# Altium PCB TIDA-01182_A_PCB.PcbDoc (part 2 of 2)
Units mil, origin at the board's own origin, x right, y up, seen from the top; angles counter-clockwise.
Board outline 4950 x 3200 mil, 4 copper layers (Component Side, Signal Layer 1, Signal Layer 2, Solder Side), stack 61.2 mil thick; 169 components, 99 nets, 868 pads, 44 vias.
Unrouted connection lines stored in the file: 4.
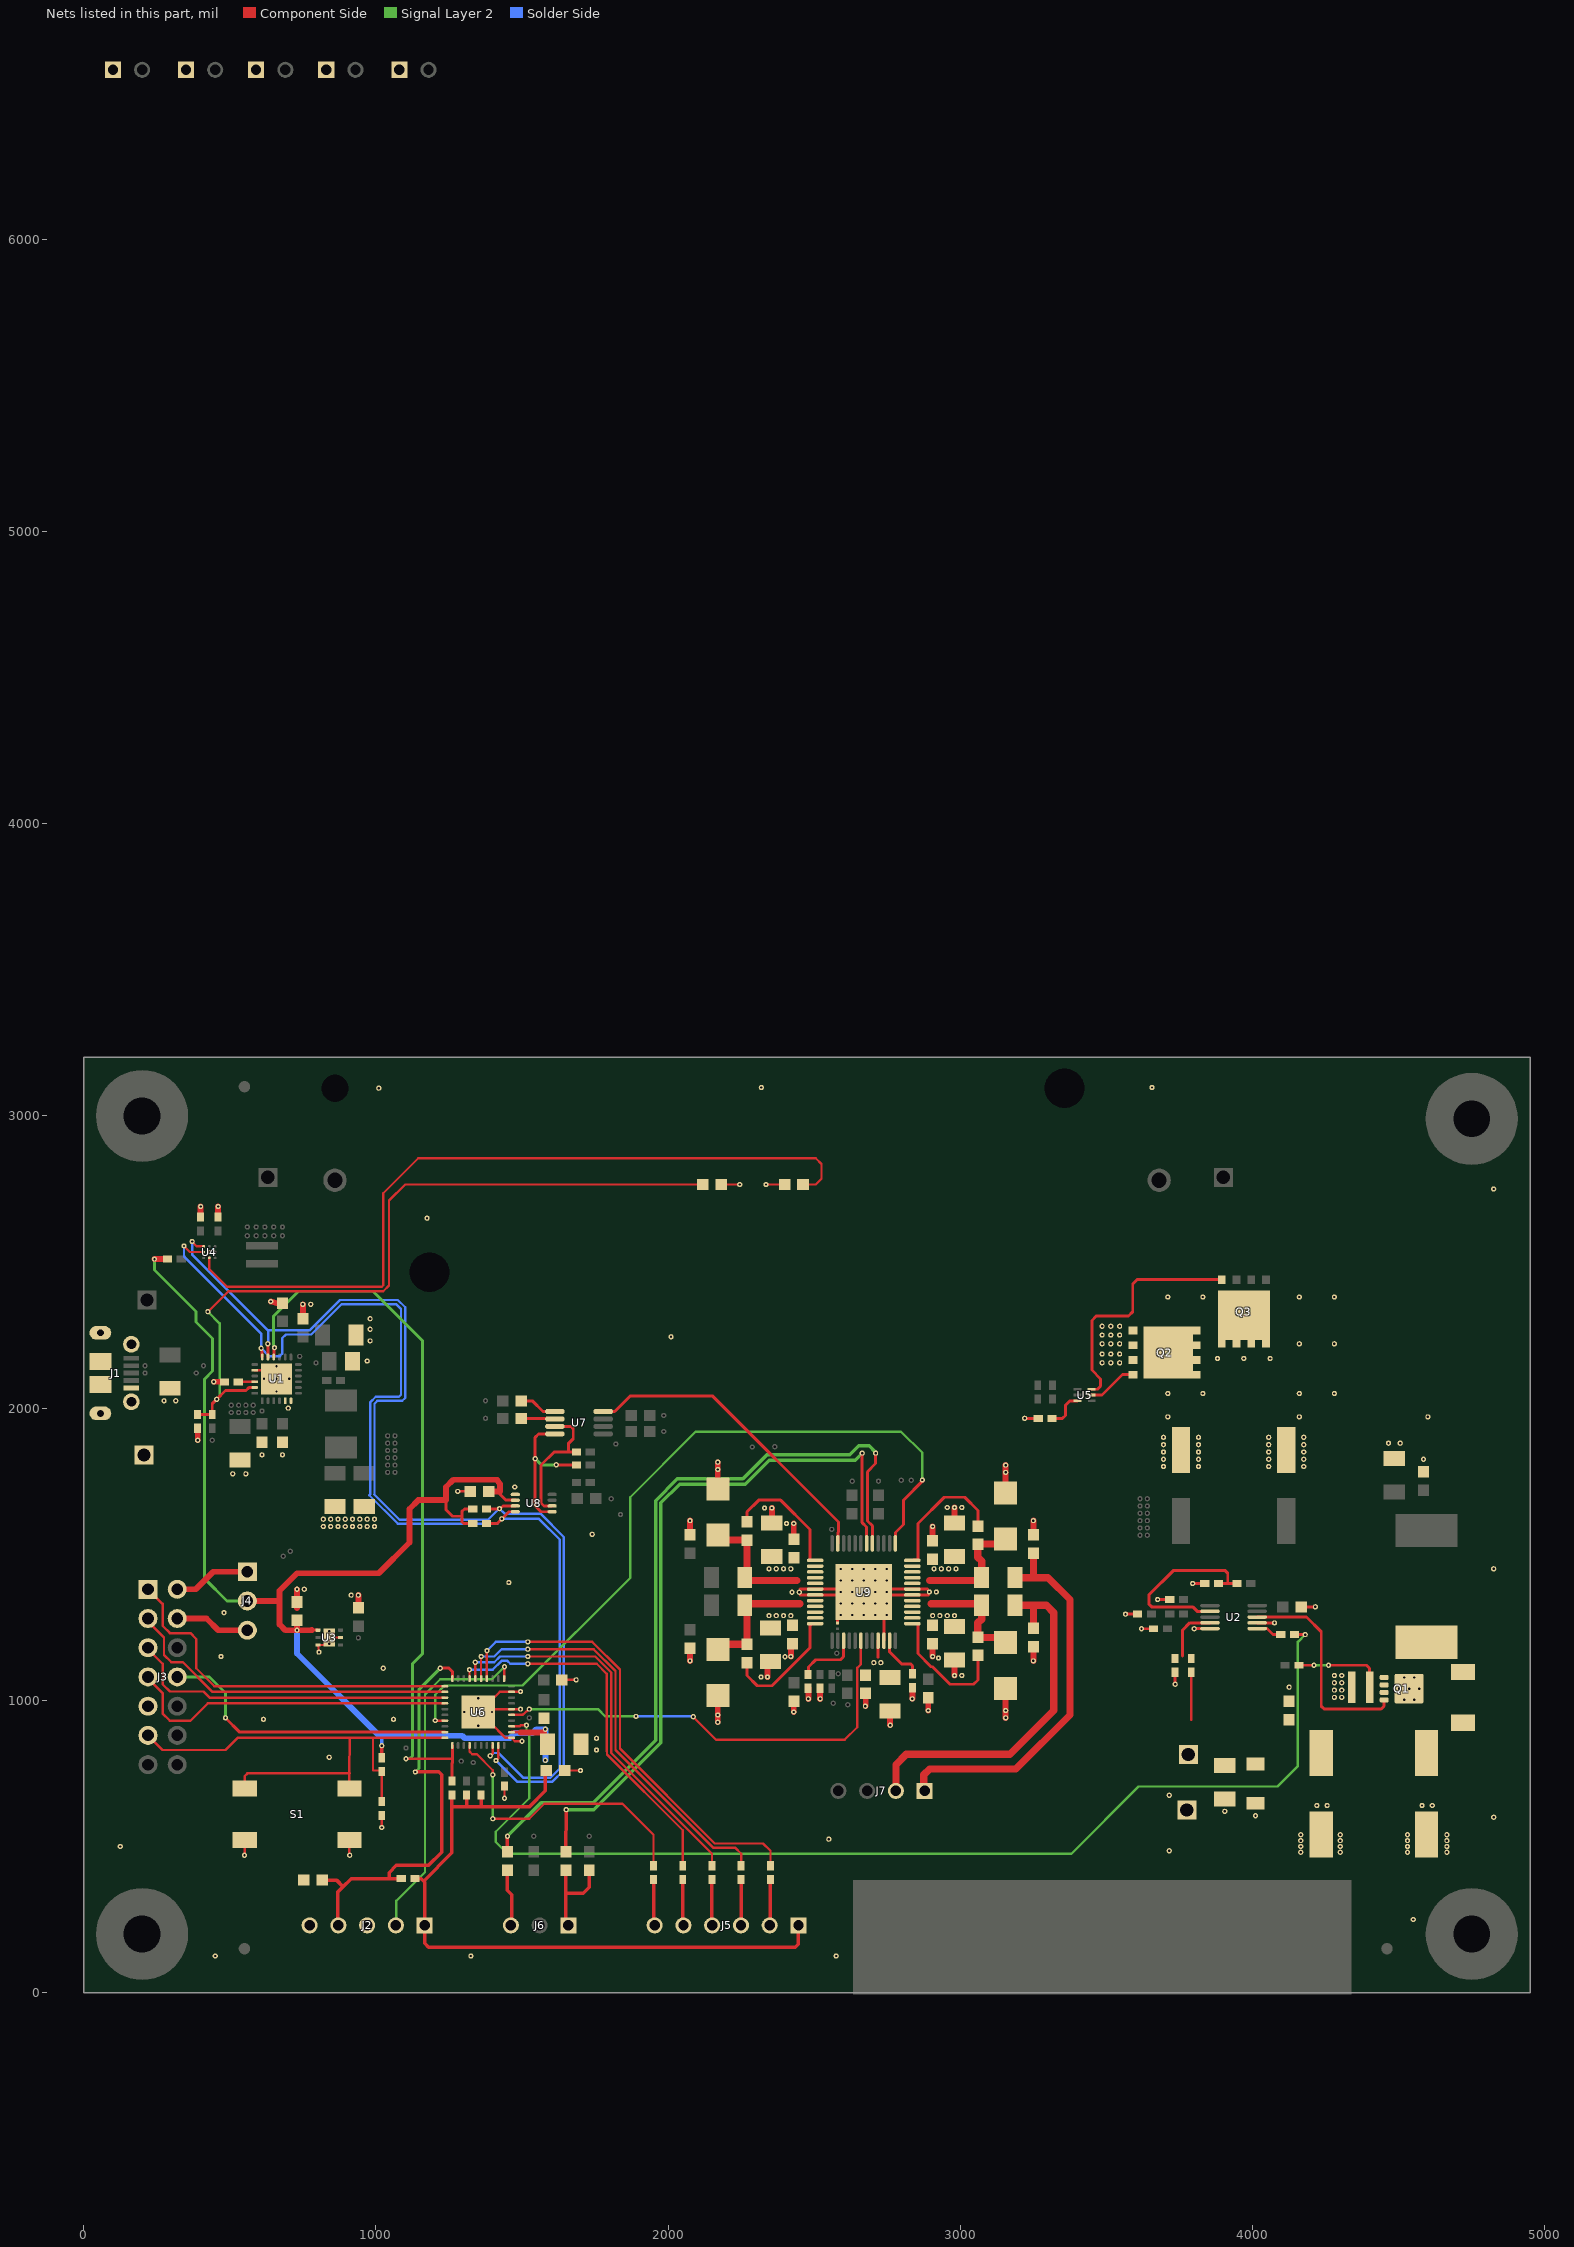
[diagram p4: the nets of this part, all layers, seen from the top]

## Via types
v1: diameter 19.68, hole 7.87, Component Side to Solder Side, 43 vias
v2: diameter 19.68, hole 7.87, Component Side to Solder Side, tented both sides, 1 vias

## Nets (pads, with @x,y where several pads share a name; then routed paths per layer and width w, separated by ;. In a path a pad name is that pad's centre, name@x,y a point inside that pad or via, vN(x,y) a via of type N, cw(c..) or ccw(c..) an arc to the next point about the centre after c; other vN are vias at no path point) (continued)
NetC50_1: C50.1 pad.3@1450,535 pad.3@2710,1846 U9.5 | length 2682.8
  Component Side w10: U9.5@2698.9,1536.97 2698.9,1597.1 2682,1614 2682,1782 2710,1810 pad.3@2710,1846
  Component Side w12: C50.1@1450,481.5 pad.3@1450,535
  Signal Layer 2 w12: pad.3@1450,535 1565,650 1744.09,650 1957,862.91 1957,1683.37 2031.63,1758 2256.09,1758 2338.09,1840 2621,1840 2652,1871 2688,1871 pad.3@2709,1850
NetC50_2: C50.2 J6.3 | length 199.7
  Component Side w12: C50.2@1450,418.5 1450,350 1465,335 J6.3@1465,225
NetC51_1: C51.1 D7.1 L3.2 U9.16 U9.17 | length 395
  Component Side w25: D7.1@2185,1545 2188.5,1548.5 C51.1@2270,1548.5 L3.2@2270,1415 ; L3.2@2265,1410 2440,1410
NetC51_2: C51.2 U9.13 | length 411.5
  Component Side w10: C51.2@2270,1611.5 2270,1645 2310,1685 2385,1685 2485,1585 U9.13@2485,1480
NetC52_1: C52.1 U9.37 | length 455
  Component Side w10: U9.37@2835.71,1262.36 2852.64,1262.36 2855,1260 2855,1160 2900,1115 2905,1115 2965,1055 3045,1055 3060,1070 C52.1@3060,1150
NetC52_2: C52.2 D9.1 L6.1 U9.40 U9.41 | length 385.3
  Component Side w25: 2900,1330 L6.1@3075,1330 ; L6.1@3072.91,1325 3072.91,1277.91 3060,1265 C52.2@3060,1216.5 3060,1215 D9.1@3155,1215
NetC53_1: C53.1 pad.3@1651,626 pad.3@2664,1846 U9.6 | length 2460.2
  Component Side w10: pad.3@2664,1846 2664,1608 2679.21,1592.79 U9.6@2679.21,1536.97
  Component Side w12: C53.1@1650,481.5 pad.3@1651,626
  Signal Layer 2 w12: pad.3@1651,626 1745.54,626 1975,855.46 1975,1675.91 2039.09,1740 2263.54,1740 2345.54,1822 2640,1822 pad.3@2664,1846 pad.3@2665,1847
NetC60_1: C60.1 D8.1 L5.2 U9.20 U9.21 | length 416.2
  Component Side w25: D8.1@2175,1190 2176.5,1191.5 C60.1@2270,1191.5 2270,1315 L5.2@2265,1320 ; L5.2@2260,1330 2450,1330
NetC60_2: C60.2 U9.24 | length 411.8
  Component Side w10: C60.2@2270,1128.5 2270,1085 2305,1050 2355,1050 2485,1180 2485,1260 U9.24@2490,1260
NetC61_1: C61.1 U9.48 | length 454.4
  Component Side w10: U9.48@2840,1480 2855,1480 2855,1605 2945,1695 3015,1695 3060,1650 C61.1@3060,1596.5
NetC61_2: C61.2 D10.1 L4.1 U9.44 U9.45 | length 382.4
  Component Side w25: 2895,1410 L4.1@3075,1410 ; L4.1@3072.91,1420 3072.91,1477.09 3060,1490 3060,1530 3065,1535 D10.1@3145,1535
NetC68_1: C68.1 J2.4 pad.3@1135,755 pad.3@1220,1110 R22.1 U6.10 | length 1470.4
  Component Side w10: pad.3@1220,1110 1250,1110 1261.42,1098.58 U6.10@1261.42,1074.17
  Component Side w12: C68.1@820,385 865,385 887.5,362.5 ; J2.4@870,235 870,345 887.5,362.5 ; R22.1@1086.38,390 1045,390 ; pad.3@1135,755 1215,755 1225,745 1225,480 1180,435 1070,435 1045,410 1045,390 ; 887.5,362.5 915,390 1045,390
  Signal Layer 2 w10: pad.3@1135,755 1147,767 1147,1036 ; 1146.5,1036.5 pad.3@1220,1110
NetD1_1: D1.1 D2.1 D3.1 D4.1 D5.1
NetD6_2: D6.2 L2.2 Q1.5 Q1.6 Q1.7 Q1.8 Q1.9@4535.59,1040
  other v1: 4518.9,1001.61 4553.39,1001.61 4501.65,1040 4536.14,1040 4518.9,1078.39 4553.39,1078.39
  other v2: 4570.63,1040
NetJ2_2: J2.2 pad.3@1440,1115 U6.1 | length 1178.4
  Component Side w8: U6.1@1438.58,1074.17 pad.3@1438.58,1113.58
  Signal Layer 2 w8: J2.2@1070,233 1070,314 1168,412 1168,1020 1220,1072 1397,1072 pad.3@1440,1115
NetJ3_1: J3.1 U6.11 | length 1255.6
  Component Side w8: J3.1@220,1380 270,1330 270,1255 295,1230 365,1230 385,1210 385,1110 446.42,1048.58 U6.11@1235.83,1048.58
NetJ3_2: J3.2 J4.1 | length 264.9
  Component Side w20: J3.2@320,1380 383.23,1380 443.23,1440 J4.1@560,1440
NetJ3_3: J3.3 U6.12 | length 1158.8
  Component Side w8: J3.3@225,1280 225,1265 275,1215 275,1155 300,1130 340,1130 441.1,1028.9 U6.12@1235.83,1028.9
NetJ3_4: J3.4 J4.3 | length 256.6
  Component Side w20: J3.4@320,1280 420,1280 460,1240 J4.3@560,1240
NetJ3_5: J3.5 U6.13 | length 1132.6
  Component Side w8: J3.5@215,1180 270,1125 270,1055 295,1030 410,1030 430.79,1009.21 U6.13@1235.83,1009.21
NetJ3_7: J3.7 U6.14 | length 1141.5
  Component Side w8: J3.7@220,1075 270,1025 270,955 295,930 365,930 424.53,989.53 U6.14@1235.83,989.53
NetJ3_8: J3.8 pad.3@485,940 U6.19 | length 1043.9
  Component Side w10: pad.3@485,940 533.9,891.1 U6.19@1235.83,891.1
  Signal Layer 2 w10: J3.8@320,1080 430,1080 485,1025 pad.3@485,940
NetJ5_2: J5.2 R28.1 | length 146.4
  Component Side w12: J5.2@2350,240 R28.1@2350,386.38
NetJ5_3: J5.3 R29.1 | length 151.4
  Component Side w12: J5.3@2250,235 R29.1@2250,386.38
NetJ5_4: J5.4 R30.1 | length 156.4
  Component Side w12: J5.4@2150,230 R30.1@2150,386.38
NetJ5_5: J5.5 R31.1 | length 151.4
  Component Side w12: J5.5@2050,235 R31.1@2050,386.38
NetJ5_6: J5.6 R33.1 | length 151.4
  Component Side w12: J5.6@1950,235 R33.1@1950,386.38
NetQ1_1: pad.3@4210,1120 pad.3@4260,1120 Q1.1 Q1.2 Q1.3 R8.2 R13.2 | length 310.7
  Component Side w10: R8.2@4158.62,1120 pad.3@4210,1120 ; pad.3@4260,1120 4390,1120 4400.51,1109.49 R13.2@4400.51,1045
  Signal Layer 2 w10: pad.3@4210,1120 pad.3@4260,1120
NetQ1_4: Q1.4 U2.8 | length 739.9
  Component Side w10: U2.8@4015.71,1285 4185,1285 4235,1235 4235,980 4245,970 4440,970 4449.96,979.96 Q1.4@4449.96,1001.61
NetQ2_4: Q2.4 U5.2 | length 170.6
  Component Side w10: U5.2@3448.5,2044.74 3484.74,2044.74 3555,2115 Q2.4@3590,2115
NetQ2_5: pad.3@3710,2050 pad.3@3710,2380 pad.3@3830,2050 pad.3@3830,2380 pad.3@3880,2170 pad.3@3970,2170 pad.3@4060,2170 pad.3@4160,2050 pad.3@4160,2220 pad.3@4160,2380 pad.3@4280,2050 pad.3@4280,2220 pad.3@4280,2380 Q2.5 Q2.6 Q2.7 Q2.8 Q2.9 Q3.5 Q3.6 Q3.7 Q3.8 Q3.9
NetQ3_4: Q3.4 U5.3 | length 826.9
  Component Side w10: U5.3@3448.5,2064.43 3469.43,2064.43 3480,2075 3480,2100 3450,2130 3450,2300 3465,2315 3575,2315 3590,2330 3590,2425 3605,2440 Q3.4@3890,2440
NetR1_1: R1.1 U1.10 | length 60.2
  Component Side w10: R1.1@525,2090 U1.10@585.2,2090.16
NetR2_1: R2.1 R3.2 U2.2 | length 655.5
  Component Side w10: U2.2@3854.29,1304.69 3810.31,1304.69 3795,1320 3655,1320 3645,1330 3645,1360 3730,1445 3905,1445 3915,1435 3915,1400 ; R3.2@3885,1400 3915,1400 ; R2.1@3946.38,1400 3915,1400
NetR4_1: pad.3@425,2330 pad.3@455,2030 R4.1 R12.2 RT1.2 U1.11 | length 2616.9
  Component Side w8: pad.3@425,2330 495,2400 1025,2400 1045,2420 1045,2710 1100,2765 RT1.2@2118.5,2765
  Component Side w10: R12.2@390,1978.62 438.62,1978.62 440,1980 440,2015 pad.3@455,2030 485,2060 555,2060 565,2070 U1.11@585,2070
  Signal Layer 2 w8: pad.3@425,2330 465,2290 465,2040 ; pad.3@456,2030 465.5,2039.5
NetR5_1: R5.1 R14.2 U2.4 | length 193.8
  Component Side w10: 3760,1151 3760,1195 3760,1240 3785.31,1265.32 U2.4@3854.29,1265.32
NetR7_2: R7.2 U2.6 | length 92.8
  Component Side w10: U2.6@4015.71,1245.63 4049.37,1245.63 4070,1225 R7.2@4096.38,1225 R7.2@4100,1225
NetR18_2: R18.2 U5.6 | length 131.6
  Component Side w10: R18.2@3315,1965 3350,1965 3360,1975 3360,2010 3375.06,2025.06 U5.6@3401.26,2025.06
NetR26_2: R26.2 U7.1 | length 131
  Component Side w10: R26.2@1496.5,2025 1535,2025 1571.61,1988.39 U7.1@1612.32,1988.39
NetR27_2: R27.2 U7.2 | length 113.6
  Component Side w10: R27.2@1496.5,1965 U7.2@1610.12,1965
NetR28_2: pad.3@1380,1170 pad.3@1520,1200 R28.2 U6.4 | length 1583.6
  Component Side w8: U6.4@1379.53,1074.17 pad.3@1379.53,1169.53 ; pad.3@1520,1200 1740,1200 1835,1105 1835,834.8 2159.8,510 2325,510 2350,485 R28.2@2350,433.62
  Solder Side w8: pad.3@1380,1170 1410,1200 pad.3@1520,1200
NetR29_2: pad.3@1360,1150 pad.3@1520,1175 R29.2 U6.5 | length 1465.5
  Component Side w8: U6.5@1359.84,1074.17 pad.3@1359.84,1149.84 ; pad.3@1520,1175 1745,1175 1820,1100 1820,830 2155,495 2230,495 2250,475 R29.2@2250,433.62
  Solder Side w8: pad.3@1360,1150 1405,1150 1430,1175 pad.3@1520,1175
NetR30_2: pad.3@1340,1130 pad.3@1520,1150 R30.2 U6.6 | length 1356.1
  Component Side w8: U6.6@1340.16,1074.17 pad.3@1340.16,1129.84 ; pad.3@1520,1150 1750.2,1150 1805,1095.2 1805,820 2150,475 R30.2@2150,433.62
  Solder Side w8: pad.3@1340,1130 1405,1130 1425,1150 pad.3@1520,1150
NetR31_2: pad.3@1320,1105 pad.3@1520,1125 R31.2 U6.7 | length 1295.7
  Component Side w8: U6.7@1320.47,1074.17 pad.3@1320.47,1104.53 ; pad.3@1520,1125 1755.4,1125 1790,1090.4 1790,825 1791,824 1791,814.2 2050,555.2 R31.2@2050,433.62
  Solder Side w8: pad.3@1320,1105 1400,1105 1430,1135 1450,1135 1460,1125 pad.3@1520,1125
NetR33_2: pad.3@1400,595 pad.3@1400,745 R33.2 U6.24 | length 1017.3
  Component Side w8: U6.24@1320.47,845.83 1320.47,824.53 1329.5,815.5 1345.5,815.5 1400,761 pad.3@1400,746 ; pad.3@1399.5,745.5 pad.3@1400,745 ; pad.3@1400,595 1525,595 1576,646 1844,646 1950,540 R33.2@1950,433.62
  Signal Layer 2 w8: pad.3@1400,592 pad.3@1400,595 pad.3@1400,745
NetR35_1: R35.1 U9.27 | length 219
  Component Side w10: R35.1@2480,1085 2480,1088.62 2480,1114 2505,1139 2590,1139 2600.47,1149.47 U9.27@2600.47,1204.29
NetR36_1: R36.1 U9.35 | length 164.2
  Component Side w10: U9.35@2757.95,1204.29 2757.95,1166.05 2799,1125 2829,1125 2836,1118 R36.1@2836,1090.62 R36.1@2836,1090
NetRT2_2: RT2.2 U4.B1 | length 2652.5
  Component Side w8: U4.B1@430,2514.32 430,2475 490,2415 1020,2415 1025,2420 1025,2735 1145,2855 2505,2855 2525,2835 2525,2785 2505,2765 RT2.2@2465,2765
NetU6_17: pad.3@1203,931 pad.3@2870,1754 U6.17 U9.1 | length 2700.6
  Component Side w8: pad.3@1203,930 1203.47,930.47 U6.17@1235.83,930.47
  Component Side w10: U9.1@2777.64,1536.97 2777.64,1574.64 2805,1602 2805,1685 pad.3@2873,1753
  Signal Layer 2 w8: pad.3@1203,931 1203,1019 1235,1051 1502,1051 1870,1419 1870,1695 2094,1919 2797,1919 2870,1847 pad.3@2870,1754
NetU6_35: pad.3@1525,970 pad.3@1890,945 pad.3@2086,944 U6.35 U9.30 | length 1551.5
  Component Side w8: U6.35@1464.17,950.16 1501.84,950.16 pad.3@1525,970 ; pad.3@2086,943 2164,865 2604,865 2647,908 2647,1111 2659.53,1123.53 U9.30@2659.53,1204.29
  Signal Layer 2 w8: pad.3@1525,970 1760,970 1785,945 pad.3@1890,945
  Solder Side w8: pad.3@1890,945 2084,945 pad.3@2085,944
NetU7_8: U7.8 U9.11 | length 1078.3
  Component Side w10: U7.8@1780,1988 1817,1988 1871,2042 2151,2042 2583,1610 2583,1577 2580.79,1574.79 U9.11@2580.79,1536.97
P-GND: C2.2 C3.2 C4.2 C5.2 C6.2 C7.2 C8.2 C9.2 C10.2 C11.2 C12.2 C13.2 C14.2 C15.2 C16.2 C17.2 C18.2 C19.2 C20.2 C22.2 C23.2 C24.2 C25.2 C26.2 C27.2 C29.2 C32.2 C34.2 C35.2 C36.2 C37.2 C38.2 C39.2 C40.2 C41.1 C45.2 C46.2 C49.1 C53.2 C54.2 C55.2 C56.2 C57.2 C58.2 C59.2 C62.2 C63.2 C64.2 C65.2 C66.2 C67.2 C68.2 D7.2 D8.2 D9.2 D10.2 J1.5 J1.6 J1.7 J1.8 J1.9 J1.10 J1.11 J2.3 J2.5 J3.9 J6.1 NT1.1 pad.3@125,500 pad.3@275,2025 pad.3@315,2025 pad.3@390,1890 pad.3@400,2690 pad.3@445,2090 pad.3@450,125 pad.3@460,2690 pad.3@470,1150 pad.3@480,1300 pad.3@510,1775 pad.3@550,470 pad.3@555,1775 pad.3@610,1840 pad.3@615,935 pad.3@640,2365 pad.3@680,1840 pad.3@700,2000 pad.3@730,1380 pad.3@750,2355 pad.3@755,1380 pad.3@777,2355 pad.3@805,1165 pad.3@820,1595 pad.3@820,1620 pad.3@840,805 pad.3@845,1595 pad.3@845,1620 pad.3@870,1595 pad.3@870,1620 pad.3@895,1595 pad.3@895,1620 pad.3@910,470 pad.3@915,1360 pad.3@920,1595 pad.3@920,1620 pad.3@940,1360 pad.3@945,1595 pad.3@945,1620 pad.3@970,1595 pad.3@970,1620 pad.3@970,2161 pad.3@980,2230 pad.3@980,2270 pad.3@980,2306 pad.3@995,1595 pad.3@995,1620 pad.3@1010,3095 pad.3@1020,565 pad.3@1025,1110 pad.3@1060,935 pad.3@1175,2650 pad.3@1280,1715 pad.3@1325,125 pad.3@1440,665 pad.3@1455,1403 pad.3@1475,1730 pad.3@1495,970 pad.3@1495,1030 pad.3@1500,860 pad.3@1685,1070 pad.3@1700,760 pad.3@1740,1568 pad.3@1755,830 pad.3@1755,870 pad.3@2010,2244 pad.3@2075,1135 pad.3@2075,1615 pad.3@2170,925 pad.3@2170,950 pad.3@2170,1790 pad.3@2170,1815 pad.3@2245,2765 pad.3@2318,1080 pad.3@2319,3097 pad.3@2330,1658 pad.3@2335,2765 pad.3@2340,1080 pad.3@2355,1658 pad.3@2400,1149 pad.3@2405,1605 pad.3@2420,1150 pad.3@2424,1370 pad.3@2430,960 pad.3@2430,1605 pad.3@2449,1370 pad.3@2480,1005 pad.3@2520,1005 pad.3@2550,525 pad.3@2575,125 pad.3@2675,980 pad.3@2760,915 pad.3@2835,1005 pad.3@2890,965 pad.3@2894,1371 pad.3@2905,1150 pad.3@2905,1595 pad.3@2918,1371 pad.3@2925,1145 pad.3@2955,1660 pad.3@2980,1085 pad.3@2980,1660 pad.3@3005,1085 pad.3@3005,1660 pad.3@3155,940 pad.3@3155,965 pad.3@3155,1780 pad.3@3155,1805 pad.3@3220,1965 pad.3@3250,1135 pad.3@3250,1615 pad.3@3485,2155 pad.3@3485,2185 pad.3@3485,2220 pad.3@3485,2250 pad.3@3485,2280 pad.3@3515,2155 pad.3@3515,2185 pad.3@3515,2220 pad.3@3515,2250 pad.3@3515,2280 pad.3@3545,2155 pad.3@3545,2185 pad.3@3545,2220 pad.3@3545,2250 pad.3@3545,2280 pad.3@3565,1295 pad.3@3620,1245 pad.3@3656,3097 pad.3@3675,1345 pad.3@3695,1800 pad.3@3695,1825 pad.3@3695,1850 pad.3@3695,1875 pad.3@3695,1900 pad.3@3710,1970 pad.3@3715,485 pad.3@3715,675 pad.3@3735,1055 pad.3@3795,1400 pad.3@3800,1245 pad.3@3815,1800 pad.3@3815,1825 pad.3@3815,1850 pad.3@3815,1875 pad.3@3815,1900 pad.3@3905,620 pad.3@4010,605 pad.3@4055,1800 pad.3@4055,1825 pad.3@4055,1850 pad.3@4055,1875 pad.3@4055,1900 pad.3@4075,1265 pad.3@4125,1045 pad.3@4160,1970 pad.3@4165,480 pad.3@4165,500 pad.3@4165,520 pad.3@4165,540 pad.3@4175,1800 pad.3@4175,1825 pad.3@4175,1850 pad.3@4175,1875 pad.3@4175,1900 pad.3@4215,1320 pad.3@4220,640 pad.3@4255,640 pad.3@4280,1010 pad.3@4280,1035 pad.3@4280,1060 pad.3@4280,1085 pad.3@4300,480 pad.3@4300,500 pad.3@4300,520 pad.3@4300,540 pad.3@4305,1010 pad.3@4305,1035 pad.3@4305,1060 pad.3@4305,1085 pad.3@4465,1880 pad.3@4505,1880 pad.3@4530,480 pad.3@4530,500 pad.3@4530,520 pad.3@4530,540 pad.3@4550,250 pad.3@4580,640 pad.3@4585,1825 pad.3@4600,1970 pad.3@4615,640 pad.3@4665,480 pad.3@4665,500 pad.3@4665,520 pad.3@4665,540 pad.3@4825,600 pad.3@4825,1450 pad.3@4825,2750 pad.4 Q2.1 Q2.2 Q2.3 R1.2 R3.1 R6.1 R12.1 R13.1 R14.1 R18.1 R35.2 R36.2 RT1.1 RT2.1 S1.1 S1.2 TP-GND1.1 TP-GND2.1 U1.8 U1.17 U1.18 U1.25 U2.5 U2.7 U3.3 U3.5 U3.7@840,1215 U4.B2 U6.31 U6.36 U6.39 U6.41 U8.1 U9.18 U9.19 U9.34 U9.42 U9.43 U9.49 | length 4020.9
  Component Side w8: pad.3@550.87,470.87 S1.2@550.87,521.42 ; U1.8@585.2,2129.53 620.53,2129.53 U1.25@621,2130 ; pad.3@805,1165 U3.3@801.61,1189.41 822.52,1189.41 828.23,1195.12 828.23,1203.23 U3.7@840,1215 U3.5@878.39,1215 ; pad.3@909.13,470.87 S1.1@909.13,521.42 ; pad.3@1020,565 C34.2@1020,606.38 ; pad.3@1280,1715 C32.2@1323.5,1715 ; U6.41@1390,925 1443.58,871.42 U6.31@1464.17,871.42 U6.31@1465,871.42 ; U6.41@1390,995 1423.9,1028.9 U6.39@1464.17,1028.9 pad.3@1493.9,1028.9 ; U6.41@1390.16,969.84 U6.36@1464.17,969.84 pad.3@1494.84,969.84 ; pad.3@1440,665 C37.2@1440,706.38 ; U6.31@1465,870 1475,860 pad.3@1500,860 ; C38.2@1636.5,1070 pad.3@1685,1070 ; C39.2@1646.5,760 pad.3@1700,760 ; RT1.1@2181.5,2765 pad.3@2245,2765 ; pad.3@2335,2765 RT2.1@2398.5,2765
  Component Side w10: 2451.53,1380.47 U9.18@2503.03,1380.47 U9.49@2599.53,1380.47 ; 2452.21,1360.79 U9.19@2503.03,1360.79 U9.49@2599.21,1360.79 ; NT1.1@2580,1265 U9.49@2580,1290 ; U9.49@2735.47,1380.47 U9.43@2835.71,1380.47 2887.53,1380.47 ; U9.34@2738.27,1204.29 U9.49@2738.27,1293.27 ; U9.49@2745.79,1360.79 U9.42@2835.71,1360.79 2890.79,1360.79 ; pad.3@3220,1965 R18.1@3266.38,1965 ; pad.3@3565,1295 R6.1@3606.38,1295 ; pad.3@3620,1245 C22.2@3661.38,1245 ; pad.3@3675,1345 C24.2@3716.38,1345 ; pad.3@3735,1055 R14.1@3735,1096.38 ; pad.3@3795,1400 R3.1@3836.38,1400 ; pad.3@3800.63,1245.63 U2.5@3854.29,1245.63 ; U2.7@4015.71,1265.32 pad.3@4074.69,1265.32 ; C23.2@4166.5,1320 pad.3@4215,1320
  Component Side w12: C53.2@1650,418.5 1650,340 ; J6.1@1655,230 1650,235 1650,340 ; C46.2@1730,418.5 1730,360 1710,340 1650,340
  Component Side w20: pad.3@390,1890 R12.1@390,1931.38 ; C29.2@400,2653.62 pad.3@400,2690 ; pad.3@445,2090 R1.2@481.38,2090 ; C25.2@460,2653.62 pad.3@460,2690 ; pad.3@640,2365 C3.2@680,2351.5 ; 730,1316.5 pad.3@730,1380 ; C5.2@750,2306.5 pad.3@750,2355 ; C26.2@940,1316.5 pad.3@940,1360 ; pad.3@2075,1135 C55.2@2075,1178.5 ; C54.2@2075,1566.5 pad.3@2075,1615 ; pad.3@2170,925 pad.3@2170,950 D8.2@2170,1016.26 ; D7.2@2170,1723.74 pad.3@2170,1790 pad.3@2170,1815 ; pad.3@2340,1080 C59.2@2340,1132.91 ; C57.2@2355,1607.09 pad.3@2355,1658 ; pad.3@2420,1150 C58.2@2420,1190 ; pad.3@2430,960 C41.1@2430,998.5 ; C56.2@2430,1551.5 pad.3@2430,1605 ; pad.3@2480,1005 R35.2@2480,1041.38 ; pad.3@2520,1005 C45.2@2520,1041.38 ; pad.3@2676,981 C35.2@2676,1023.5 ; pad.3@2759.37,915.63 C36.2@2759.37,963.54 ; pad.3@2836,1006 R36.2@2836,1043.38 ; pad.3@2890,965 C49.1@2890,1008.5 ; pad.3@2905,1150 C63.2@2905,1193.5 ; C65.2@2905,1546.5 pad.3@2905,1595 ; pad.3@2980,1085 C62.2@2980,1137.91 ; C64.2@2980,1607.09 pad.3@2980,1660 ; pad.3@3155,940 pad.3@3155,965 D9.2@3155,1041.26 ; D10.2@3155,1708.74 pad.3@3155,1780 pad.3@3155,1805 ; pad.3@3250,1135 C66.2@3250,1183.5 ; C67.2@3250,1566.5 pad.3@3250,1615
  other v1: 1350,912.76 1302.76,960 1350,960 1397.24,960 1350,1007.24 840,1193.35 840,1236.65 2590.63,1291.89 2630,1291.89 2669.37,1291.89 2708.74,1291.89 2748.11,1291.89 2590.63,1331.26 2630,1331.26 2669.37,1331.26 2708.74,1331.26 2748.11,1331.26 2590.63,1370.63 2630,1370.63 2669.37,1370.63 2708.74,1370.63 2748.11,1370.63 2590.63,1410 2630,1410 2669.37,1410 2708.74,1410 2748.11,1410 2590.63,1449.37 2630,1449.37 2669.37,1449.37 2708.74,1449.37 2748.11,1449.37 660,2056.69 616.69,2100 660,2100 703.31,2100 660,2143.31
RSPKR+: C66.1 J7.2 L6.2 | length 1260.5
  Component Side w25: J7.2@2780,685 2780,780 2815,815 3170,815 3320,965 3320,1300 3295,1325 L6.2@3190,1325 ; C66.1@3250,1246.5 3250,1320
RSPKR-: C67.1 J7.1 L4.2 | length 1324.5
  Component Side w25: J7.1@2875,700 2875,745 2895,765 3190,765 3375,950 3375,1345 3300,1420 3250,1420 ; L4.2@3190,1420 3250,1420 ; C67.1@3250,1503.5 3250,1420
RST: C34.1 J3.11 R32.1 S1.3 S1.4 U6.20 | length 1864.4
  Component Side w8: J3.11@220,880 270,830 485,830 526.42,871.42 U6.20@1235.83,871.42 ; S1.4@550.87,698.58 550.87,740.87 560,750 909.13,750 ; S1.3@909.13,698.58 909.13,750 ; 910,750 909.13,750 ; 910,870 909.13,750 ; 990,869.13 990,760 R32.1@1015,760 ; C34.1@1020,655 R32.1@1020,755
SCL1: pad.3@371,2570 pad.3@630,2220 pad.3@1411,794 pad.3@1423,1656 R21.1 U1.5 U4.A3 U6.29 U8.3 | length 3779.4
  Component Side w8: pad.3@371,2569 386.32,2553.68 U4.A3@410.32,2553.68 ; pad.3@1411,793 1418.9,800.9 U6.29@1418.9,845.83
  Component Side w10: pad.3@630,2220 U1.5@630.47,2174.8 ; R21.1@1378.62,1655 1425,1655 1435.16,1665.16 U8.3@1477.01,1665.16
  Solder Side w8: pad.3@371,2570 371,2526 631,2266 ; pad.3@630,2220 631,2221 631,2266 ; 994.5,1704.5 1081,1618 1384,1618 pad.3@1423,1657 ; 995,1705 995,2015 1005,2025 1090,2025 1100,2035 1100,2345 1075,2370 877,2370 773,2266 631,2266 ; pad.3@1411,794 1484,721 1603,721 1643,761 1643,1559 1563,1639 1440,1639 pad.3@1424,1655
SCL2: R24.1 U7.3 U8.6 | length 464.8
  Component Side w10: U8.6@1602.99,1665.16 1575,1665.16 1565,1675.16 1565,1805 1610,1850 1658.43,1850 ; U7.3@1612.32,1937.2 1667.8,1937.2 1675.32,1929.68 1675.32,1895 1658.43,1878.11 1658.43,1850 ; R24.1@1686.38,1850 1658.43,1850
SD: pad.3@1515,915 pad.3@4180,1225 R7.1 U6.33 | length 3886.9
  Component Side w8: U6.33@1464.17,910.79 1491.79,910.79 1496,915 pad.3@1515,915
  Component Side w10: R7.1@4143.62,1225 pad.3@4180,1225
  Signal Layer 2 w8: pad.3@1515,915 1515,895 1525,885 1525,665 1410,550 1410,515 1450,475 3380,475 3610,705 4085,705 4155,775 4155,1200 pad.3@4180,1225
SDA1: pad.3@343,2555 pad.3@607,2205 pad.3@1391,810 pad.3@1431,1621 R20.1 U1.6 U4.A2 U6.28 U8.4 | length 3851.9
  Component Side w8: pad.3@343,2554 363,2534 U4.A2@410.32,2534 ; pad.3@1391,810 1399.21,818.21 U6.28@1399.21,845.83
  Component Side w10: pad.3@607,2205 610.79,2191.21 U1.6@610.79,2174.8 ; R20.1@1378.62,1605 1414.98,1605 1455.45,1645.47 U8.4@1477.01,1645.47 ; pad.3@1391,809 pad.3@1391.5,809.5
  Solder Side w8: pad.3@343,2555 343,2519 608,2254 pad.3@608,2204 ; pad.3@607,2205 pad.3@608,2204 ; 977.1,1702.1 1075.2,1604 1415,1604 pad.3@1432,1621 ; 980,1705 980,1940 981,1941 981,2020.8 999.2,2039 1079,2039 1086,2046 1086,2339 1069,2356 882.8,2356 778.8,2252 692,2252 679,2239 679,2186 670,2177 635,2177 pad.3@608,2204 ; pad.3@1392,810 1402,820 1419,820 1503,736 1504,736 ; pad.3@1431,1621 pad.3@1432,1621 ; 1504,735 1597.2,735 1629,766.8 1629,1550 1558,1621 pad.3@1432,1621
SDA2: pad.3@1545,1827 pad.3@1617,1806 R23.1 U7.4 U8.5 | length 520.2
  Component Side w10: U8.5@1602.99,1645.47 1564.68,1645.47 1545,1665.16 pad.3@1545,1827 1545,1900 1556.61,1911.61 U7.4@1612.32,1911.61 ; pad.3@1620,1805 R23.1@1686.38,1805
  Signal Layer 2 w10: pad.3@1545,1827 1566,1806 pad.3@1617,1806
STAT: pad.3@653,2207 pad.3@1103,800 R11.1 U1.4 U6.21 | length 2497.8
  Component Side w10: U1.4@650.16,2174.8 651,2175.65 651,2203 pad.3@654,2206 ; pad.3@1103,800 1260,800 ; R11.1@1260,725 1260,785 1261.42,786.42 U6.21@1261.42,845.83
  Signal Layer 2 w10: pad.3@650,2205 650,2315 735,2400 990,2400 1160,2230 1160,1159.79 1124.61,1124.39 ; pad.3@1103,800 1116,800 1125,809 1125,1124
V25: C27.1 C32.1 C39.1 C40.1 J2.1 J4.2 J5.1 pad.3@242,2510 pad.3@730,1240 pad.3@1020,845 pad.3@1580,795 pad.3@1580,901 R9.2 R10.2 R11.2 R17.2 R20.2 R21.2 R22.2 R32.2 R34.2 U3.1 U6.32 U8.2 | length 6926.5
  Component Side w10: 669.84,1336.26 669.84,1343.74 ; 780.59,1240.59 U3.1@801.61,1240.59 ; 1240,1685 1240,1652.15 1262.15,1630 1295.02,1630 ; R20.2@1331.38,1605 1300,1605 1295.02,1609.98 1295.02,1630 ; R21.2@1331.38,1655 1302.76,1655 1295.02,1647.26 1295.02,1630 ; 1425,1715 1425,1705 1445.16,1684.84 U8.2@1477.01,1684.84 ; U6.32@1464.17,891.1 1493.9,891.1
  Component Side w12: R32.2@1020,803.62 pad.3@1020,845 ; R22.2@1140,390 1155,390 1163.5,381.5 ; 1163,381 1163.5,381.5 ; R11.2@1260,676.38 1260,635 ; R10.2@1310,676.38 1310,635 ; 1360,640 R9.2@1360,676.38 ; C39.1@1580,760 1580,690 1525,635 1310,635 ; J5.1@2445,230 2445,165 2435,155 1180,155 1166.85,168.15 J2.1@1166.85,230 1166.85,378.15 1163.5,381.5 ; 1163.5,381.5 1260,478 1260,635 ; 1260,635 1310,635
  Component Side w20: pad.3@242,2510 R17.2@286.38,2510 ; J4.2@560,1340 666.1,1340 669.84,1343.74 669.84,1374.84 730,1435 1010,1435 1115,1540 1115,1655 1145,1685 1240,1685 1240,1730 1265,1755 1415,1755 1425,1740 1425,1715 C32.1@1386.5,1715 ; 669.84,1260 669.84,1336.26 ; 670,1260 690,1240 pad.3@730,1240 ; 730,1253.5 pad.3@730,1240 ; 780.59,1240.59 780,1240 pad.3@730,1240 ; 1495,890 1575,890 1573.9,891.1
  Signal Layer 2 w10: pad.3@242,2510 242,2473 384,2331 384,2295 441,2238 441,2127 414,2100 414,1416 490,1340 J4.2@560,1340
  Solder Side w12: pad.3@1020,845 1020,879
  Solder Side w20: pad.3@730,1240 730,1160 1011,879 1020,879 1295,879 1304,870 1458,870 1476,888 1536,888 1549,901 pad.3@1579,901 ; pad.3@1579,900 pad.3@1580,901 pad.3@1580,795
VCC: C14.1 C15.1 C16.1 C17.1 C18.1 C35.1 C36.1 C56.1 C57.1 C58.1 C59.1 C62.1 C63.1 C64.1 C65.1 D6.1 pad.3@2345,1290 pad.3@2345,1450 pad.3@2370,1290 pad.3@2370,1450 pad.3@2395,1290 pad.3@2395,1450 pad.3@2420,1290 pad.3@2420,1450 pad.3@2704,1129 pad.3@2728,1129 pad.3@2905,1290 pad.3@2910,1450 pad.3@2930,1290 pad.3@2935,1450 pad.3@2955,1290 pad.3@2960,1450 pad.3@2980,1290 pad.3@2985,1450 R5.2 TP-9.5.1 U9.14 U9.15 U9.22 U9.23 U9.33 U9.38 U9.39 U9.46 U9.47 | length 216.9
  Component Side w10: 2718.58,1147.42 U9.33@2718.58,1204.29 ; 3790,935 R5.2@3790,1095
pads on no net: BT1.MH1 BT1.MH2 BT1.MH3 D1.2 D2.2 D3.2 D4.2 D5.2 FID1.1 FID2.1 FID3.1 H1.1 H2.1 H3.1 H4.1 J1.4 J3.6 J3.10 J3.12 J3.13 J3.14 Logo1.0 Q1.9@4501.65,1013.92 Q1.9@4501.65,1066.08 Q1.9@4522.89,1040 Q1.9@4536.14,1013.92 Q1.9@4536.14,1066.08 Q1.9@4556.26,1001.61 Q1.9@4556.26,1027.2 Q1.9@4556.26,1052.8 Q1.9@4556.26,1078.39 SH-J1.0 U1.12 U3.2 U3.7@840,1197.28 U3.7@840,1232.72 U5.1 U6.2 U6.3 U6.8 U6.9 U6.15 U6.16 U6.18 U6.25 U6.26 U6.27 U6.37 U6.38 U9.31 U9.32

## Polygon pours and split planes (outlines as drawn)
P-GND on Signal Layer 1 "SIGNAL_LAYER_1_P-GND_P000" (solid, remove dead copper, pour order 0): 50,3150 50,50 4900,50 4900,3150 50,3150
A-GND on Solder Side "SOLDER_SIDE_A-GND_P002" (solid, remove dead copper, pour order 2): 2830,1862 2025,1862 2025,2055 1340,2055 1340,1650 2505,1650 2505,940 2830,940
P-GND on Solder Side "SOLDER_SIDE_P-GND_P012" (solid, remove dead copper, pour order 12): 11.67,32.54 11.67,3182.54 4911.67,3182.54 4911.67,32.54 11.67,32.54
VCC on Signal Layer 2 "SIGNAL_LAYER_2_VCC_P004" (solid, remove dead copper, pour order 4): 3885,750 3885,990 3875,1000 3320,1555 2280,1555 2280,1035 3235,1035 3520,750
P-GND on Signal Layer 2 "SIGNAL_LAYER_2_P-GND_P006" (solid, remove dead copper, pour order 6): 25,25 25,3175 4925,3175 4925,25 25,25
P-GND on Component Side "COMPONENT_SIDE_P-GND_P010" (solid, remove dead copper, pour order 10): 64.24,-41.31 64.24,3108.69 4964.24,3108.69 4964.24,-41.31 64.24,-41.31

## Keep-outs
Keep-Out Layer:
  text ".Layer_Name" at 577,-858.49 h60

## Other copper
Component Side:
  rectangle net NetC33_1: 1635,1690 1690,1750
  rectangle net NetC52_2: 2834,1315 2936,1347
  rectangle net NetC60_1: 2405,1316 2504,1347
  rectangle net NetC51_1: 2405,1394 2502,1426
  rectangle net P-GND: 2405,1355 2501,1386
  rectangle net P-GND: 2878,1356 2937,1385
  rectangle net NetC61_2: 2836,1394 2937,1425
  rectangle net VCC: 2305,1276 2503,1308
  rectangle net A-GND: 2545,968 2632,1044
  rectangle net AVDD_5V: 2545,1075 2613,1106
  rectangle net VCC: 2674,1066 2744,1155
  rectangle net VCC: 2313,1434 2502,1465
  rectangle net VCC: 2836,1434 3018,1465
  rectangle net VCC: 2835,1278 3015,1306
  rectangle net VCC: 3695,739 4766,950
  rectangle net NetD6_2: 4487,981 4764,1254
  rectangle net NetQ1_1: 4388,1017 4465,1100
  rectangle net P-GND: 4260,991 4352,1100
  rectangle net P-GND: 4105,990 4145,1060
  rectangle net P-GND: 3695,460 4685,695
  rectangle net NetC6_1: 3590,1520 4700,1740
  rectangle net P-GND: 3655,1765 4625,1995
  rectangle net NetR5_1: 3725,1130 3800,1180
  rectangle net NetQ2_5: 3625,2030 4310,2405
  rectangle net NetBT1_2: 3530,2495 4060,2915
  rectangle net NetBT1_2: 3930,2425 4060,2540
  rectangle net P-GND: 3470,2150 3605,2280
  rectangle net VCC: 2885,1435 3015,1495
  rectangle net VCC: 2885,1245 3015,1305
  rectangle net VCC: 2320,1440 2445,1505
  rectangle net VCC: 2315,1235 2445,1305
  rectangle net NetC4_1: 730,2215 840,2265
  rectangle net NetC1_1: 730,1990 980,2075
  rectangle net NetC6_1: 645,1925 675,2030
  rectangle net P-GND: 685,1990 715,2055
  rectangle net NetC6_1: 650,1925 795,1975
  rectangle net NetC6_1: 725,1750 1085,1930
  rectangle net NetC19_1: 495,1925 635,2030
  rectangle net P-GND: 495,1775 700,1890
  rectangle net P-GND: 790,1580 1035,1700
  rectangle net P-GND: 260,2010 330,2100
  rectangle net 5V: 205,2160 335,2210
  rectangle net NetBT1_1: 530,2670 995,2885
  rectangle net NetBT1_1: 720,2430 995,2885
  rectangle net NetBT1_1: 535,2430 770,2505
  rectangle net NetC19_1: 535,2545 700,2655
  rectangle net P-GND: 15,1955 105,2285
  rectangle net P-GND: 75,1990 195,2075
  rectangle net P-GND: 856,2201 1005,2334
  rectangle net P-GND: 1690,810 1775,890
  rectangle net V25: 1540,740 1605,960
  rectangle net NetC4_1: 755,2172 801,2225
  rectangle net P-GND: 731,2299 828,2380
  text ".Layer_Name" at 577,-858.49 h60
Signal Layer 2:
  rectangle net NetC19_1: 495,1925 635,2030
  rectangle net NetC19_1: 535,2545 700,2655
  rectangle net NetC19_1: 479,1925 589,2655
Solder Side:
  rectangle net NetC6_1: 3280,1525 3675,1735
  rectangle net NetC6_1: 1006.26,1750 1315,2010
  rectangle net NetC6_1: 3270,1525 3460,2625
  rectangle net NetC6_1: 1505,2345 3460,2625
  rectangle net NetC6_1: 1120,2070 1915,2371
  rectangle net NetC6_1: 1500,2145 1915,2625
  rectangle net NetQ2_5: 3696,2031 4308,2404
  rectangle net NetD6_2: 4480,980 4760,1260
  rectangle net NetC6_1: 1115,1750 1325,2365
  text ".Layer_Name" at 577,-858.49 h60

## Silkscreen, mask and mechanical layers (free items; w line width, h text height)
Top Overlay:
  region: 4840,2630 4540,2630 4540,2530 4840,2530
  text "LITHIUM ION" at 1340,2850 h50
  text "18650" at 1340,2780 h50
  text "POS+" at 1050,2750 h60
  text "NEG-" at 3270,2750 h60
  text "3.7V 2000mA" at 1330,2710 h50
  text "'.PRJ_Number'.PCB_Rev-" at 3900,2550 h108.27
  text "USB" at 70,1790 h50 r90
  text "B" at 625,1360 h50
  text "A" at 625,1265 h50
  text "A=SYS PWR (DEFAULT)" at 490,1105 h40
  text "B=JTAG PWR" at 490,1050 h40
  text "RESET" at 620,760 h50
  text "SPEAKERS" at 2985,590 h50
  text "JTAG" at 170,500 h50
  text "(-L+)(+R-)" at 2510,490 h50
  text "PWR/VOLUME" at 720,30 h50
  text "AUX" at 1500,30 h50
  text "LEDS" at 2110,30 h50
  text ".Layer_Name" at 577,-858.49 h60
Bottom Overlay:
  text ".Layer_Name" at 577,-858.49 h60
Top Paste:
  text ".Layer_Name" at 577,-858.49 h60
Bottom Paste:
  text ".Layer_Name" at 577,-858.49 h60
Top Solder:
  text ".Layer_Name" at 577,-858.49 h60
  text ".Layer_Name" at 577,-858.49 h60
Bottom Solder:
  text ".Layer_Name" at 577,-858.49 h60
Drill Guide:
  text ".Layer_Name" at 577,-858.49 h60
M1 Board Outline:
  the board outline again, w10
  text ".Layer_Name" at 577,-858.49 h60
M2 Board Dimensions:
  rectangle: 0,-275 125,-150
  rectangle: 125,-400 500,-275
  lines w7: 0,-275 1000,-275 ; 125,-400 125,-150 ; 250,-400 250,-150 ; 500,-400 500,-150 ; 750,-400 750,-150 ; 0,-400 1000,-400 1000,-150 0,-150 0,-400
  text ".Layer_Name" at 577,-858.49 h60
M3 3D STEP Top:
  text ".Layer_Name" at 577,-858.49 h60
M4 3D STEP Bottom:
  text ".Layer_Name" at 577,-858.49 h60
M5 Assembly Top:
  lines w10: -292,-930.17 6308,-930.17 ; -292,-726.83 6310,-726.83 ; -292,-523.5 -292,-1133.5 3713,-1133.5 6310,-1133.5 6310,-523.5 -291.5,-523.5 -291.5,-1133.5 1284,-1133.5 ; 2173,-1133.5 2173,-523.5 ; 3440,-726.83 3440,-523.5 ; 4280,-726.83 4280,-523.5 ; 4902,-1140 4902,-937.17
  text "COMPONENTS MARKED 'DNP' SHOULD NOT BE POPULATED." at 1153.5,-318.5 h60
  text "ASSEMBLY VARIANT:" at 1153,-434 h60
  text ".VariantName" at 2189,-434 h60
  text "PCB VIEWED FROM TOP SIDE" at -228.5,-655.67 h60
  text "BOARD #:" at 2248,-655.67 h60
  text ".PRJ_Number" at 2793.5,-655.67 h60
  text "REV:" at 3638,-655.67 h60
  text ".PCB_Rev" at 3929.5,-655.67 h60
  text "SVN REV:" at 4476,-655.67 h60
  text ".VersionControl_RevNumber" at 4982,-655.67 h60
  text "TID #:" at 2248,-859 h60
  text ".TID" at 2793.5,-859 h60
  text "PLOT NAME =" at -228.5,-1064.34 h60
  text ".plot_File_Name" at 577,-1064.34 h60
  text "GENERATED    :" at 2250,-1064.34 h60
  text ".Print_Date" at 3119.5,-1064.34 h60
  text ".Print_Time" at 3848.5,-1064.34 h60
  text "TEXAS INSTRUMENTS" at 5113,-1064.34 h60
M6 Assembly Bottom:
  lines w10: -292.5,-727.33 6309.5,-727.33 ; -290.5,-930.67 6309.5,-930.67 ; 1115.5,-1140.5 1115.5,-937.67 ; 1737.5,-727.33 1737.5,-524 ; 2577.5,-727.33 2577.5,-524 ; 3844.5,-1134 3844.5,-524 ; 4733.5,-1134 6309,-1134 6309,-524 -292.5,-524 -292.5,-1134 2304.5,-1134 6309.5,-1134 6309.5,-524
  text "COMPONENTS MARKED 'DNP' SHOULD NOT BE POPULATED." at 6102,-318 h60
  text ".VariantName" at 5058,-434 h60
  text "ASSEMBLY VARIANT:" at 6097,-434 h60
  text ".VersionControl_RevNumber" at 1035.5,-656.17 h60
  text "SVN REV:" at 1541.5,-656.17 h60
  text ".PCB_Rev" at 2088,-656.17 h60
  text "REV:" at 2379.5,-656.17 h60
  text ".PRJ_Number" at 3224,-656.17 h60
  text "BOARD #:" at 3769.5,-656.17 h60
  text "PCB VIEWED FROM BOTTOM SIDE" at 6246,-656.17 h60
  text ".TID" at 3224,-859.5 h60
  text "TID #:" at 3769.5,-859.5 h60
  text "TEXAS INSTRUMENTS" at 904.5,-1064.84 h60
  text ".Print_Time" at 2169,-1064.84 h60
  text ".Print_Date" at 2898,-1064.84 h60
  text "GENERATED    :" at 3767.5,-1064.84 h60
  text ".plot_File_Name" at 5440.5,-1064.84 h60
  text "PLOT NAME =" at 6246,-1064.84 h60
M9 Title Sheet:
  drawing of 57 lines, arcs and shapes, not listed
  text "1" at 739.84,8036.5 h70
  text "2" at 3235.5,8036.5 h70
  text "3" at 5724.84,8036.5 h70
  text "4" at 8231.51,8036.5 h70
  text "5" at 10730.5,8036.5 h70
  text "6" at 13235.5,8036.5 h70
  text "A" at -416.5,6893.5 h70
  text "A" at 14383.5,6893.5 h70
  text "B" at -416.5,4513.5 h70
  text "B" at 14383.5,4513.5 h70
  text "C" at -416.5,2138.5 h70
  text "C" at 14383.5,2138.5 h70
  text "PROJECT TITLE:" at 11343.5,277.5 h45
  text ".PRJ_Title" at 11393.5,144.17 h70
  text "DESIGNED FOR:" at 11343.5,-23.5 h45
  text ".PRJ_Customer" at 11393.5,-163.5 h70
  text "D" at -416.5,-231.5 h70
  text "D" at 14383.5,-231.5 h70
  text "FILE NAME:" at 11343.5,-323.5 h45
  text ".PCB_File_Name_No_Path" at 11393.5,-443.5 h70
  text "Texas Instruments (TI) and/or its licensors do not warrant the accuracy or completeness of this specification" at 6374,-605.34 h45
  text "ENGINEER:" at 11343.5,-613.5 h45
  text "LAYOUT BY:" at 12848.5,-613.5 h45
  text "or any information contained therein. TI and/or its licensors do not warrant that this design will meet" at 6329.01,-718 h45
  text ".PRJ_Engineer" at 11393.5,-768.49 h70
  text ".PCB_Layout" at 12899,-768.49 h70
  text "the specifications, will be suitable for your application or fit for any particular purpose, or will operate in" at 6329.01,-830.67 h45
  text ".Layer_Name" at 577,-858.49 h60
  text "ALTIUM DESIGNER VERSION:" at 12848.5,-923.5 h45
  text "an implementation. TI and/or its licensors do not warrant that the design is production worthy. You should" at 6329.01,-943.33 h45
  text "completely validate and test your design implementation to confirm the system functionality for your application." at 6374,-1056 h45
  text ".print_Scale" at 11393.5,-1056.83 h70
  text ".Application_BuildNumber" at 12899,-1056.83 h70
  text "1" at 739.84,-1263.5 h70
  text "2" at 3235.5,-1263.5 h70
  text "3" at 5724.84,-1263.5 h70
  text "4" at 8231.51,-1263.5 h70
  text "5" at 10730.5,-1263.5 h70
  text "6" at 13235.5,-1263.5 h70
M10 Fab Notes:
  drawing of 173 lines, arcs and shapes, not listed
  text "DESIGN INFORMATION" at 12378.02,6201 h60
  text "MIN. TRACK WIDTH:" at 11733.46,6021 h60
  text "6" at 12829.7,6021 h60
  text "MIL" at 12984.46,6021 h60
  text "6" at 12824.7,5891 h60
  text "MIL" at 12979.46,5891 h60
  text "MIN. CLEARANCE:" at 11733.46,5889 h60
  text "MIN. VIA PAD SIZE:" at 11733.46,5757 h60
  text "18" at 12799.71,5757 h60
  text "MIL" at 12984.46,5757 h60
  text "0.05mm (2MIL)" at 12428.46,5615.29 h60
  text "MINIMUM ANNULAR RING" at 11404.23,5611 h60
  text "EXTERNAL" at 13136.46,5611 h60
  text "PER" at 11604.23,5493 h60
  text "IPC-D-275 CLASS 2 LEVEL C" at 11824.23,5493 h60
  text "MIL, HOLES" at 13312.46,5380.71 h60
  text "+/-" at 12920,5380 h60
  text "+/-" at 13774,5380 h60
  text "REGISTRATION TOLERANCES:" at 11404.23,5375 h60
  text "METAL" at 12604,5375 h60
  text "5" at 13180.2,5375 h60
  text "3" at 14013.2,5375 h60
  text "MIL" at 14129.46,5375 h60
  text "+/-" at 13774,5262 h60
  text "HOLE SIZE TOLERANCE (UNLESS OTHERWISE SPECIFIED):" at 11404.23,5257 h60
  text "3" at 14013.2,5257 h60
  text "MIL" at 14129.46,5257 h60
  text "MATERIAL:" at 11329.46,5047.54 h60
  text "FR-4 High Tg" at 12315.9,4907.21 h60
  text "FR-408" at 11750.46,4898.64 h60
  text "OTHER" at 13238.46,4898.64 h60
  text "X" at 12161,4895 h60
  text "62 MIL (1.6mm) +/-10%" at 12070.56,4735.92 h60
  text "THICKNESS:" at 11404.23,4731.64 h60
  text "X" at 11942.4,4731.64 h60
  text "OTHER" at 13355.46,4731.64 h60
  text "TOLERANCE:" at 11404.23,4573.64 h60
  text "X" at 12243.53,4573.64 h60
  text "ANSI IPC-6012 TYPE 3 CLASS 2" at 12430.48,4573.64 h60
  text "OTHER +/-" at 12430.46,4417.64 h60
  text "BOW & TWIST:" at 11404.23,4260.64 h60
  text "X" at 12243.53,4260.64 h60
  text "ANSI IPC-6012 TYPE 3 CLASS 2" at 12430.48,4260.64 h60
  text "OTHER +/-" at 12430.46,4102.13 h60
  text "DRILLING:" at 11329.46,3963.64 h60
  text "REFERENCE:" at 11404.23,3846.64 h60
  text "X" at 12052.46,3846.64 h60
  text "AS SHOWN" at 12239.46,3846.64 h60
  text "X" at 12953.46,3846.64 h60
  text "NC_DRILL FILES" at 13090.46,3846.64 h60
  text "PTH COPPER THICKNESS:" at 11404.23,3688.64 h60
  text "X" at 12534.46,3688.64 h60
  text "20-30 um" at 12671.46,3688.64 h60
  text "OTHER" at 13388.46,3688.64 h60
  text "BOARD FINISH:" at 11329.46,3529.64 h60
  text "SILKSCREEN:" at 11484.68,3411.64 h60
  text "X" at 12433.46,3411.64 h60
  text "TOP" at 12559.46,3411.64 h60
  text "X" at 12943.46,3411.64 h60
  text "BOTTOM" at 13070.46,3411.64 h60
  text "SILKSCREEN COLOR:" at 11484.68,3244.64 h60
  text "X" at 12432.42,3244.64 h60
  text "WHITE" at 12559.46,3244.64 h60
  text "OTHER" at 13070.46,3244.64 h60
  text "GREEN" at 12690.46,3085.44 h60
  text "OTHER" at 13308.46,3085.44 h60
  text "BLUE" at 13668.46,3085.44 h60
  text "X" at 13145,3080 h60
  text "SOLDER RESIST COLOR:" at 11484.68,3074.64 h60
  text "X" at 12563.42,2915.44 h60
  text "MATTE" at 12690.46,2915.44 h60
  text "SEMI-GLOSS" at 13308,2914.8 h60
  text "IMMERSION GOLD (ENIG)" at 12390.46,2726.92 h60
  text "ENEPIG" at 13728,2723.64 h60
  text "SURFACE FINISH:" at 11329.46,2722.64 h60
  text "X" at 12203.51,2722.64 h60
  text "IMM. TIN/SILVER OR EQUIV" at 11659,2565.64 h60
  text "OTHER" at 13090.46,2565.64 h60
  text "ARRAY/PANEL:" at 11329.46,2386.64 h60
  text "CUT AND TRIM PER M1 BOARD OUTLINE" at 12390.46,2382.35 h60
  text "N.C. ROUTE" at 12390.46,2230.64 h60
  text "X" at 13069.46,2230.64 h60
  text "V. SCORE" at 13256.46,2230.64 h60
  text "CERTIFICATION:" at 11329.46,2093.64 h60
  text "MATERIALS AND WORKMANSHIP FOR ALL PCBS" at 12054.46,2093.64 h60
  text "TO MEET OR EXCEED THE REQUIREMENTS OF:" at 12054.46,1995.64 h60
  text "X" at 11680.96,1859.13 h60
  text "ANSI IPC-A-600F CLASS ->" at 11819.96,1859.13 h60
  text "X" at 13459.02,1859.13 h60
  text "2" at 13577.96,1859.14 h60
  text "1" at 13262.96,1857.64 h60
  text "3" at 13931.96,1857.64 h60
  text "X" at 12495.02,1699.64 h60
  text "RoHS" at 12631.96,1699.64 h60
  text "OTHER" at 13276.36,1699.64 h60
  text "PER ORDER" at 13673.42,1699.64 h60
  text "ALL BOARDS MUST MEET OR EXCEED UL94-V0 REQUIREMENTS." at 11357,1534 h60
  text "PCB MUST BEAR THE UL94V-0 UL REGISTERED MATERIAL ID NUMBER" at 11357,1414 h60
  text "ADDITIONAL REQUIREMENTS:" at 11329.46,1240.64 h60
  text "MICROSECTION:" at 11404.23,1125.64 h60
  text "YES" at 12309.96,1125.64 h60
  text "REQUIRED" at 13171.46,969.49 h60
  text "BARE BOARD ELEC. TEST:" at 11404.23,966.64 h60
  text "NONE" at 12709.96,966.64 h60
  text "X" at 13044.46,966.64 h60
  text "PER ORDER" at 13763.46,966.64 h60
  text ".Layer_Name" at 577,-858.49 h60
M11 Gerber Information:
  lines w10: -292,-930.17 6308,-930.17 ; -292,-726.83 6310,-726.83 ; -292,-523.5 -292,-1133.5 3713,-1133.5 6310,-1133.5 6310,-523.5 -291.5,-523.5 -291.5,-1133.5 1284,-1133.5 ; 2173,-1133.5 2173,-523.5 ; 3440,-726.83 3440,-523.5 ; 4280,-726.83 4280,-523.5 ; 4902,-1140 4902,-937.17
  text "ALL ARTWORK VIEWED FROM TOP SIDE" at -228.5,-655.67 h60
  text "BOARD #:" at 2248,-655.67 h60
  text ".PRJ_Number" at 2793.5,-655.67 h60
  text "REV:" at 3638,-655.67 h60
  text ".PCB_Rev" at 3929.5,-655.67 h60
  text "SVN REV:" at 4476,-655.67 h60
  text ".VersionControl_RevNumber" at 4982,-655.67 h60
  text "LAYER NAME =" at -228.5,-858.49 h60
  text "TID #:" at 2248,-859 h60
  text ".TID" at 2793.5,-859 h60
  text "PLOT NAME =" at -228.5,-1064.34 h60
  text ".plot_File_Name" at 577,-1064.34 h60
  text "GENERATED    :" at 2250,-1064.34 h60
  text ".Print_Date" at 3119.5,-1064.34 h60
  text ".Print_Time" at 3848.5,-1064.34 h60
  text "TEXAS INSTRUMENTS" at 5113,-1064.34 h60
M12 Stackup:
  drawing of 295 lines, arcs and shapes, not listed
  text "Layer" at 9797.84,7830 h60
  text "Name" at 10207.76,7830 h60
  text "Material" at 11147.5,7830 h60
  text "Thickness" at 12007.26,7830 h60
  text "Constant" at 12657.1,7830 h60
  text "Board Layer Stack" at 13226.96,7830 h60
  text "1" at 9797.84,7710 h60
  text "Top Overlay" at 10207.76,7710 h60
  text "2" at 9797.84,7590 h60
  text "Top Solder" at 10207.76,7590 h60
  text "Solder Resist" at 11147.5,7590 h60
  text "0.40mil" at 12007.26,7590 h60
  text "3.5" at 12657.1,7590 h60
  text "3" at 9797.84,7470 h60
  text "Component Side" at 10207.76,7470 h60
  text "Copper" at 11147.5,7470 h60
  text "2.80mil" at 12007.26,7470 h60
  text "4" at 9797.84,7350 h60
  text "Dielectric 1" at 10207.76,7350 h60
  text "FR-4 High Tg" at 11147.5,7350 h60
  text "12.00mil" at 12007.26,7350 h60
  text "4.8" at 12657.1,7350 h60
  text "5" at 9797.84,7230 h60
  text "Signal Layer 1" at 10207.76,7230 h60
  text "Copper" at 11147.5,7230 h60
  text "2.80mil" at 12007.26,7230 h60
  text "6" at 9797.84,7110 h60
  text "Dielectric 4" at 10207.76,7110 h60
  text "FR-4 High Tg" at 11147.5,7110 h60
  text "26.00mil" at 12007.26,7110 h60
  text "4.2" at 12657.1,7110 h60
  text "7" at 9797.84,6990 h60
  text "Signal Layer 2" at 10207.76,6990 h60
  text "Copper" at 11147.5,6990 h60
  text "2.80mil" at 12007.26,6990 h60
  text "8" at 9797.84,6870 h60
  text "Dielectric 3" at 10207.76,6870 h60
  text "FR-4 High Tg" at 11147.5,6870 h60
  text "12.00mil" at 12007.26,6870 h60
  text "4.2" at 12657.1,6870 h60
  text "9" at 9797.84,6750 h60
  text "Solder Side" at 10207.76,6750 h60
  text "Copper" at 11147.5,6750 h60
  text "2.80mil" at 12007.26,6750 h60
  text "10" at 9797.84,6630 h60
  text "Bottom Solder" at 10207.76,6630 h60
  text "Solder Resist" at 11147.5,6630 h60
  text "0.40mil" at 12007.26,6630 h60
  text "3.5" at 12657.1,6630 h60
  text "11" at 9797.84,6510 h60
  text "Bottom Overlay" at 10207.76,6510 h60
  text ".Layer_Name" at 577,-858.49 h60
M13 Component Bodies Top:
  text ".Layer_Name" at 577,-858.49 h60
M14 Component Bodies Bottom:
  text ".Layer_Name" at 577,-858.49 h60
M15 Courtyards Top:
  text ".Layer_Name" at 577,-858.49 h60
M16 Courtyards Bottom:
  text ".Layer_Name" at 577,-858.49 h60
Drill Drawing:
  circle w10: c5363.72,2898.64 r16.58
  circle w10: c5363.72,2898.64 r27.63
  circle w10: c5363.72,1904.08 r27.63
  lines w10: 5336.09,1752.14 5363.72,1765.95 5391.34,1752.14 5377.53,1779.76 5391.34,1807.39 5363.72,1793.58 5336.09,1807.39 5349.9,1779.76 5336.09,1752.14 ; 5336.09,2028.4 5363.72,2000.78 5391.34,2028.4 5363.72,2056.03 5336.09,2028.4 ; 5336.09,2180.35 5391.34,2180.35 5363.72,2125.1 5336.09,2180.35 ; 5336.09,2304.67 5391.34,2304.67 5363.72,2249.42 5336.09,2304.67 ; 5336.09,2373.74 5391.34,2373.74 5391.34,2428.99 5336.09,2428.99 5336.09,2373.74 ; 5336.09,2498.06 5391.34,2498.06 5391.34,2553.31 5336.09,2553.31 5336.09,2498.06 ; 5336.09,2636.19 5349.9,2636.19 5363.72,2622.38 5377.53,2636.19 5391.34,2636.19 5377.53,2650 5391.34,2663.82 5377.53,2663.82 5363.72,2677.63 5349.9,2663.82 5336.09,2663.82 5349.9,2650 5336.09,2636.19 ; 5336.09,2746.7 5363.72,2760.51 5391.34,2746.7 5377.53,2774.32 5391.34,2801.95 5363.72,2788.14 5336.09,2801.95 5349.9,2774.32 5336.09,2746.7 ; 5336.09,3009.15 5349.9,3009.15 5349.9,2995.34 5377.53,2995.34 5377.53,3009.15 5391.34,3009.15 5391.34,3036.78 5377.53,3036.78 5377.53,3050.59 5349.9,3050.59 5349.9,3036.78 5336.09,3036.78 5336.09,3009.15 ; 5336.09,3119.66 5336.09,3133.47 5349.9,3147.28 5336.09,3161.1 5336.09,3174.91 5349.9,3174.91 5363.72,3161.1 5377.53,3174.91 5391.34,3174.91 5391.34,3161.1 5377.53,3147.28 5391.34,3133.47 5391.34,3119.66 5377.53,3119.66 5363.72,3133.47 5349.9,3119.66 5336.09,3119.66 ; 5336.09,3257.79 5349.9,3257.79 5349.9,3243.98 5377.53,3243.98 5377.53,3257.79 5391.34,3257.79 5391.34,3285.42 5377.53,3285.42 5377.53,3299.23 5349.9,3299.23 5349.9,3285.42 5336.09,3285.42 5336.09,3257.79 ; 5347.14,2169.3 5380.29,2169.3 5363.72,2136.15 5347.14,2169.3 ; 5347.14,2509.11 5380.29,2509.11 5380.29,2542.26 5347.14,2542.26 5347.14,2509.11 ; 5347.14,2757.75 5363.72,2766.04 5380.29,2757.75 5372.01,2774.32 5380.29,2790.9 5363.72,2782.61 5347.14,2790.9 5355.43,2774.32 5347.14,2757.75 ; 5347.14,3014.68 5355.43,3014.68 5355.43,3006.39 5372.01,3006.39 5372.01,3014.68 5380.29,3014.68 5380.29,3031.25 5372.01,3031.25 5372.01,3039.54 5355.43,3039.54 5355.43,3031.25 5347.14,3031.25 5347.14,3014.68
  lines w12: 5286,1714.84 8632.65,1714.84 ; 5286,3331 8632.65,3331 ; 5623.86,1590.52 5623.86,3455.32 ; 5955.86,1590.52 5955.86,3455.32 ; 6592.43,1590.52 6592.43,3455.32 ; 6851.57,1590.52 6851.57,3455.32 ; 7226.72,1590.52 7226.72,3455.32 ; 8066.22,1590.52 8066.22,3455.32 ; 5286,1590.52 8632.65,1590.52 8632.65,3455.32 5286,3455.32 5286,1590.52
  text "Symbol" at 5360.59,3368.3 h72
  text "Quantity" at 5661.16,3368.3 h72
  text "Finished Hole Size" at 5993.16,3368.3 h72
  text "Plated" at 6629.72,3368.3 h72
  text "Hole Type" at 6888.86,3368.3 h72
  text "Drill Layer Pair" at 7264.02,3368.3 h72
  text "Hole Tolerance" at 8103.51,3368.3 h72
  text "1" at 5661.16,3243.98 h60
  text "93.50mil (2.375mm)" at 5993.16,3243.98 h60
  text "NPTH" at 6629.72,3243.98 h60
  text "Round" at 6888.86,3243.98 h60
  text "Component Side - Solder Side" at 7264.02,3243.98 h60
  text "2" at 5661.16,3119.66 h60
  text "136.00mil (3.454mm)" at 5993.16,3119.66 h60
  text "NPTH" at 6629.72,3119.66 h60
  text "Round" at 6888.86,3119.66 h60
  text "Component Side - Solder Side" at 7264.02,3119.66 h60
  text "1" at 5661.16,2995.34 h60
  text "6.00mil (0.152mm)" at 5993.16,2995.34 h60
  text "PTH" at 6629.72,2995.34 h60
  text "Round" at 6888.86,2995.34 h60
  text "Component Side - Solder Side" at 7264.02,2995.34 h60
  text "44" at 5661.16,2871.02 h60
  text "7.87mil (0.200mm)" at 5993.16,2871.02 h60
  text "PTH" at 6629.72,2871.02 h60
  text "Round" at 6888.86,2871.02 h60
  text "Component Side - Solder Side" at 7264.02,2871.02 h60
  text "352" at 5661.16,2746.7 h60
  text "8.00mil (0.203mm)" at 5993.16,2746.7 h60
  text "PTH" at 6629.72,2746.7 h60
  text "Round" at 6888.86,2746.7 h60
  text "Component Side - Solder Side" at 7264.02,2746.7 h60
  text "2" at 5661.16,2622.38 h60
  text "33.46mil (0.850mm)" at 5993.16,2622.38 h60
  text "PTH" at 6629.72,2622.38 h60
  text "Round" at 6888.86,2622.38 h60
  text "Component Side - Solder Side" at 7264.02,2622.38 h60
  text "10" at 5661.16,2498.06 h60
  text "35.00mil (0.889mm)" at 5993.16,2498.06 h60
  text "PTH" at 6629.72,2498.06 h60
  text "Round" at 6888.86,2498.06 h60
  text "Component Side - Solder Side" at 7264.02,2498.06 h60
  text "18" at 5661.16,2373.74 h60
  text "35.43mil (0.900mm)" at 5993.16,2373.74 h60
  text "PTH" at 6629.72,2373.74 h60
  text "Round" at 6888.86,2373.74 h60
  text "Component Side - Solder Side" at 7264.02,2373.74 h60
  text "17" at 5661.16,2249.42 h60
  text "40.00mil (1.016mm)" at 5993.16,2249.42 h60
  text "PTH" at 6629.72,2249.42 h60
  text "Round" at 6888.86,2249.42 h60
  text "Component Side - Solder Side" at 7264.02,2249.42 h60
  text "6" at 5661.16,2125.1 h60
  text "45.28mil (1.150mm)" at 5993.16,2125.1 h60
  text "PTH" at 6629.72,2125.1 h60
  text "Round" at 6888.86,2125.1 h60
  text "Component Side - Solder Side" at 7264.02,2125.1 h60
  text "2" at 5661.16,2000.78 h60
  text "52.00mil (1.321mm)" at 5993.16,2000.78 h60
  text "PTH" at 6629.72,2000.78 h60
  text "Round" at 6888.86,2000.78 h60
  text "Component Side - Solder Side" at 7264.02,2000.78 h60
  text "4" at 5661.16,1876.46 h60
  text "125.98mil (3.200mm)" at 5993.16,1876.46 h60
  text "PTH" at 6629.72,1876.46 h60
  text "Round" at 6888.86,1876.46 h60
  text "Component Side - Solder Side" at 7264.02,1876.46 h60
  text "2" at 5661.16,1752.14 h60
  text "23.62mil (0.600mm)" at 5993.16,1752.14 h60
  text "PTH" at 6629.72,1752.14 h60
  text "Slot" at 6888.86,1752.14 h60
  text "Component Side - Solder Side" at 7264.02,1752.14 h60
  text "461 Total" at 5661.16,1627.82 h60
  text "Slot definitions :" at 5360.59,1540.79 h60
  text "Routed Path Length" at 5811.31,1540.79 h60
  text "= Calculated from tool start centre position to tool end centre position." at 6351.05,1540.79 h60
  text "Hole Length" at 5811.31,1491.07 h60
  text "= Routed Path Length + Tool Size = Slot length as defined in the PCB layout" at 6151.24,1491.07 h60
  text ".Layer_Name" at 577,-858.49 h60
M17 Embedded Cavity:
  text ".Layer_Name" at 577,-858.49 h60
M18 Embedded Assembly:
  text ".Layer_Name" at 577,-858.49 h60
M19 Embedded Keepout:
  text ".Layer_Name" at 577,-858.49 h60

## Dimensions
0,-400 to 1000,-400 on M2 Board Dimensions
0,0 to 0,3200 on M2 Board Dimensions
0,0 to 4950,0 on M2 Board Dimensions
